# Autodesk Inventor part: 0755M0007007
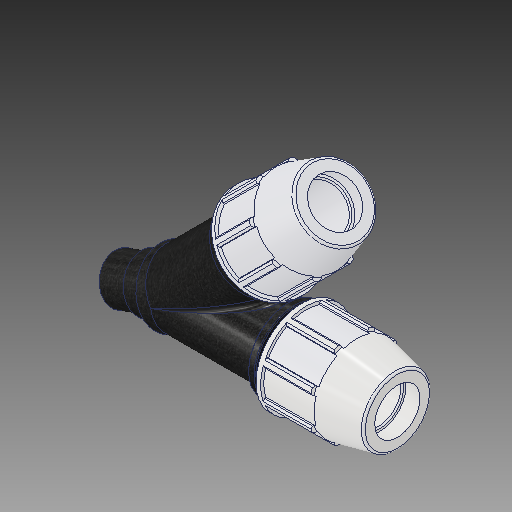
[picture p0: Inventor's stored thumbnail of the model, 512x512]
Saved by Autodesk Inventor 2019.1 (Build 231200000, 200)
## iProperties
Created: 2017-02
Part Number: 0755M0007007
Material: PVC-Piping
Description: PLASSON Y FITTING 3/4'' - 3/4'' - 3/4''M
Document SubType Name: Modeling
Designer: KIM
Mass: 92.6774 g
Surface Area: 199.44 cm^2
Volume: 66.1981 cm^3
Density: 1.4 g/cm^3
Appearance: PTFE
Author: KIM
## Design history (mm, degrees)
derived "0755M0.ipt"
feature "Solid1::0755M0.ipt"
tag "TaggingFeature1"
body "Solid1"
other parameters: "d2" = 26.6, "d4" = 10.414, "d5" = 24.9936, "d7" = 53.848, "d11" = 4.1656, "d13" = 120 deg, "d14" = 39.9, "d15" = 12 deg, "d16" = 46.84776, "d18" = 1.33, "d19" = 35 deg, "d20" = 17.5 deg, "d21" = 50.07864, "d23" = 0, "d25" = 360 deg, "d27" = 1.07696, "d33" = 0.532, "d42" = 31.242, "d43" = 1.61544, "d46" = 0.798, "d51" = 124.968, "d68" = 4.1656, "d91" = 40.386, "d93" = 57.912, "d95" = 18.5087, "d98" = 2.6924, "d99" = 0, "d101" = 45 deg, "d103" = 2.6924, "d104" = 160 deg, "d105" = 26.441, "d106" = 30.40715, "d107" = 17.78, "d108" = 30.2895, "d109" = 18.5087, "d110" = 40.386, "d111" = 9.08685, "d113" = 0.52882, "d116" = 1.07696, "d_" = 26.6, "E_" = 53.848, "A_" = 124.968, "l_" = 57.912, "l_2" = 17.78, "R_" = 26.441
